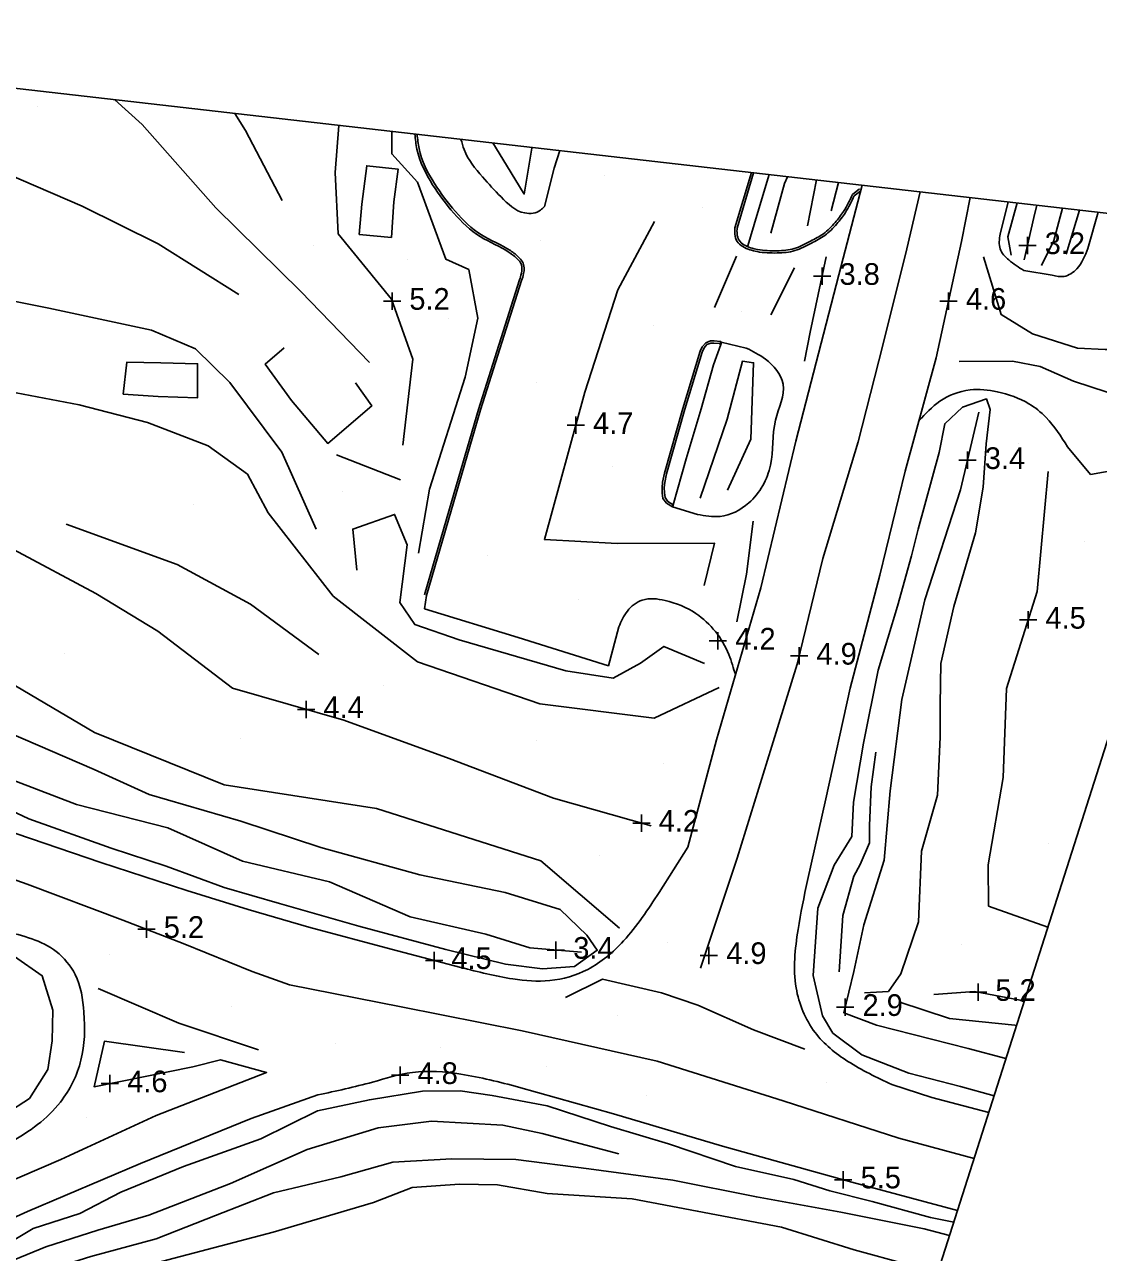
# Model space of a CAD drawing. Extents: x 2316231 to 2323598, y 363169 to 371906.
# Drawn here: x 2321056.2 to 2321303.9, y 371622.5 to 371905.8 of the extents above; entities that cross this region are included whole.
import ezdxf

# ---------------------------------------------------------------- set-up
doc = ezdxf.new("R2010")
doc.units = 0
for name, color, linetype in [('RD_DTM_BkLn1', 7, 'Continuous'), ('RD_DTM_Spot', 7, 'Continuous'), ('RD_DTM_TinHull', 7, 'Continuous'), ('RD_DTM_Void', 7, 'Continuous'), ('RD_EX_H2O', 7, 'Continuous'), ('RD_EX_Road', 7, 'Continuous')]:
    doc.layers.add(name, color=color, linetype=linetype)

msp = doc.modelspace()

# ---------------------------------------------------------------- linework, layer by layer
at = {"layer": 'RD_DTM_BkLn1'}
for p, q in [((2321238.863, 371869.97), (2321236.844, 371859.376)), ((2321242.317, 371862.865), (2321243.955, 371869.387)), ((2321299.568, 371863.027), (2321296.495, 371852.85)), ((2321220.457, 371852.373), (2321215.373, 371840.523)), ((2321228.33, 371838.829), (2321233.828, 371849.672)), ((2321142.92, 371800.768), (2321128.145, 371806.595))]:
    msp.add_line(p, q, dxfattribs=at)
for points in [[(2321200.755, 371720.962), (2321178.245, 371727.364), (2321154.142, 371736.473), (2321129.827, 371745.326), (2321104.183, 371752.718), (2321086.946, 371765.902), (2321072.634, 371774.586), (2321053.696, 371784.724), (2321034.554, 371792.143), (2321011.385, 371803.02), (2321000.166, 371815.454), (2320989.235, 371838.029), (2320977.702, 371852.426), (2320975.22, 371867.477), (2320972.951, 371892.004), (2320973.482, 371900.318)], [(2321112.371, 371793.18), (2321107.677, 371802.058), (2321098.592, 371808.631), (2321084.549, 371813.986), (2321068.841, 371818.114), (2321046.119, 371822.417), (2321024.011, 371829.564), (2321007.375, 371838.157), (2320996.479, 371853.659), (2320986.474, 371871.338), (2320983.378, 371890.851), (2320983.909, 371899.126)], [(2321123.505, 371789.385), (2321115.531, 371807.167), (2321103.554, 371823.224), (2321095.62, 371830.979), (2321085.469, 371835.306), (2321061.783, 371840.373), (2321027.056, 371847.321), (2321012.224, 371866.047), (2321004.626, 371893.2), (2321004.563, 371896.764)], [(2321179.795, 371701.686), (2321167.05, 371705.574), (2321147.408, 371709.681), (2321124.582, 371715.945), (2321106.121, 371722.053), (2321084.963, 371728.189), (2321072.242, 371733.98), (2321052.524, 371742.465), (2321033.56, 371748.576), (2321015.618, 371753.723), (2320995.155, 371760.812), (2320974.152, 371769.177), (2320964.545, 371785.417), (2320960.663, 371805.94), (2320959.939, 371816.706), (2320943.255, 371819.849), (2320920.857, 371823.589), (2320896.492, 371835.56), (2320868.581, 371846.187), (2320850.246, 371852.06), (2320835.078, 371861.975), (2320822.796, 371874.183), (2320812.266, 371892.11), (2320812.342, 371893.23)], [(2321105.623, 371843.544), (2321087.022, 371855.221), (2321069.488, 371863.914), (2321044.636, 371874.603), (2321035.867, 371886.718), (2321034.459, 371893.345)], [(2321135.753, 371827.86), (2321119.95, 371844.246), (2321100.36, 371863.574), (2321083.372, 371882.745), (2321077.025, 371888.477)], [(2321115.627, 371865.261), (2321107.198, 371881.354), (2321104.685, 371885.314)], [(2321143.509, 371808.807), (2321145.762, 371828.601), (2321140.821, 371842.465), (2321128.592, 371857.566), (2321127.901, 371871.66), (2321128.689, 371882.569)], [(2321140.954, 371881.166), (2321140.921, 371875.976), (2321146.82, 371869.46), (2321153.358, 371851.722), (2321158.665, 371849.306), (2321160.776, 371838.098), (2321157.851, 371824.484), (2321149.618, 371798.624), (2321147.06, 371783.874)], [(2321173.309, 371877.466), (2321173.239, 371877.284), (2321171.49, 371866.72), (2321167.354, 371873.389), (2321164.227, 371878.505)], [(2321228.358, 371857.668), (2321231.491, 371869.122), (2321232.222, 371870.729)], [(2321212.11, 371688.1), (2321220.62, 371713.468), (2321228.573, 371739.318), (2321234.427, 371758.248), (2321240.386, 371782.664), (2321248.521, 371809.528), (2321254.21, 371831.891), (2321259.758, 371854.103), (2321262.814, 371867.231)], [(2321285.187, 371864.672), (2321283.063, 371856.882), (2321283.806, 371852.652)], [(2321290.84, 371850.248), (2321293.679, 371855.996), (2321295.676, 371863.473)], [(2321213.008, 371776.409), (2321215.383, 371786.152), (2321192.924, 371786.064), (2321176.133, 371787.013), (2321185.446, 371821.002), (2321193.058, 371844.636), (2321201.494, 371860.386)], [(2321277.418, 371852.203), (2321281.511, 371838.905), (2321288.731, 371834.446), (2321299.098, 371831.134), (2321305.469, 371830.836), (2321310.617, 371830.872), (2321315.251, 371845.27), (2321319.644, 371860.416), (2321319.73, 371860.722)], [(2321241.163, 371852.239), (2321237.467, 371834.894), (2321236.116, 371828.133)], [(2321212.042, 371796.586), (2321218.276, 371814.801), (2321221.794, 371828.132), (2321224.371, 371827.8), (2321223.779, 371810.167), (2321218.403, 371798.4)], [(2321271.834, 371828.088), (2321284.079, 371828.184), (2321290.48, 371826.941), (2321298.15, 371823.541), (2321305.919, 371820.981), (2321313.887, 371820.322), (2321322.478, 371820.302), (2321328.803, 371821.825), (2321332.136, 371822.687)], [(2321277.354, 371799.081), (2321278.073, 371809.068), (2321278.976, 371817.012), (2321278.105, 371819.468), (2321272.607, 371817.566), (2321268.496, 371813.741), (2321267.204, 371807.084), (2321262.374, 371789.397), (2321260.794, 371783.279), (2321257.567, 371771.604), (2321253.153, 371756.913), (2321249.752, 371740.056), (2321247.399, 371726.403), (2321247.08, 371718.503), (2321242.975, 371711.911), (2321239.175, 371701.955), (2321238.106, 371686.426), (2321240.252, 371677.086), (2321242.701, 371673.148), (2321249.345, 371668.156), (2321260.173, 371663.919), (2321272.082, 371660.795), (2321279.857, 371658.702)], [(2321292.342, 371802.696), (2321289.805, 371775.013), (2321282.692, 371752.636), (2321281.929, 371732.109), (2321278.518, 371711.961), (2321278.585, 371702.436), (2321292.249, 371697.57)], [(2321277.354, 371799.081), (2321275.582, 371788.576), (2321270.558, 371771.59), (2321267.59, 371758.395), (2321267.458, 371748.953), (2321267.422, 371741.436), (2321266.845, 371728.04), (2321263.084, 371715.096), (2321262.395, 371698.782), (2321258.372, 371686.774), (2321255.486, 371682.765), (2321249.986, 371682.462)], [(2321213.067, 371758.433), (2321203.684, 371762.346), (2321198.325, 371758.458), (2321191.964, 371755.009), (2321181.038, 371756.703), (2321156.444, 371763.877), (2321146.206, 371767.398), (2321142.772, 371772.463), (2321144.434, 371785.806), (2321141.562, 371792.828), (2321131.921, 371789.424), (2321132.887, 371779.962)], [(2321124.124, 371760.514), (2321108.301, 371772.103), (2321091.435, 371781.281), (2321065.78, 371790.587)], [(2321224.275, 371791.266), (2321222.737, 371779.054), (2321220.518, 371767.991)], [(2321179.795, 371701.686), (2321185.884, 371695.729), (2321188.337, 371692.258), (2321183.106, 371688.486), (2321175.679, 371687.939), (2321167.189, 371689.068), (2321153.378, 371692.449), (2321133.336, 371697.819), (2321114.998, 371703.074), (2321102.287, 371706.763), (2321088.883, 371711.682), (2321076.175, 371715.803), (2321057.228, 371722.579), (2321045.229, 371728.155), (2321025.735, 371735.156), (2321007.369, 371741.601), (2320988.308, 371748.938), (2320969.756, 371757.218), (2320953.885, 371763.355)], [(2321244.135, 371687.298), (2321244.954, 371700.261), (2321247.534, 371709.36), (2321248.94, 371712.036), (2321251.144, 371717.052), (2321251.1, 371721.068), (2321251.531, 371729.936), (2321252.598, 371737.925)], [(2321275.234, 371644.2), (2321257.916, 371648.864), (2321231.207, 371657.534), (2321202.108, 371666.629), (2321170.999, 371673.694), (2321143.068, 371679.232), (2321117.292, 371684.266), (2321108.744, 371687.322), (2321092.83, 371693.786), (2321078.916, 371699.222), (2321056.815, 371707.489), (2321037.611, 371714.29)], [(2321051.92, 371654.492), (2321057.335, 371658.017), (2321061.557, 371664.714), (2321062.569, 371671.384), (2321062.696, 371678.398), (2321060.25, 371686.351), (2321053.905, 371690.793)], [(2321236.233, 371669.443), (2321224.356, 371673.862), (2321211.53, 371679.548), (2321203.156, 371682.45), (2321189.554, 371685.561), (2321180.994, 371681.368)], [(2321110.168, 371669.266), (2321091.824, 371675.443), (2321073.176, 371683.455)], [(2321265.963, 371682.055), (2321275.376, 371682.73), (2321285.845, 371680.736), (2321286.768, 371680.377)], [(2321257.875, 371680.369), (2321269.558, 371676.499), (2321284.617, 371674.989), (2321285.018, 371674.889)], [(2320771.018, 371541.569), (2320783.675, 371550.404), (2320801.239, 371560.761), (2320826.41, 371568.664), (2320849.036, 371574.832), (2320874.491, 371581.496), (2320897.809, 371588.162), (2320921.351, 371595.165), (2320947.344, 371602.117), (2320966.599, 371608.471), (2320994.344, 371617.396), (2321011.536, 371622.642), (2321028.89, 371629.323), (2321045.554, 371635.787), (2321064.61, 371643.963), (2321086.608, 371654.116), (2321112.049, 371664.025), (2321101.375, 371666.954), (2321095.027, 371665.337), (2321072.235, 371660.757), (2321074.638, 371671.271), (2321093.099, 371668.677)], [(2321051.665, 371624.122), (2321058.169, 371628.06), (2321068.988, 371631.515), (2321078.381, 371636.427), (2321092.859, 371642.391), (2321110.677, 371648.743), (2321123.804, 371655.206), (2321135.75, 371657.755), (2321148.007, 371659.73), (2321156.704, 371659.837), (2321164.086, 371658.727), (2321176.77, 371656.381), (2321191.4, 371651.582), (2321204.751, 371647.609), (2321220.23, 371642.384), (2321233.646, 371639.356), (2321241.975, 371636.769), (2321251.764, 371634.29), (2321265.198, 371630.561), (2321270.563, 371629.546)], [(2321193.285, 371645.255), (2321175.608, 371649.98), (2321166.563, 371651.871), (2321150.122, 371652.83), (2321137.763, 371651.299), (2321121.365, 371646.281), (2321103.712, 371638.434), (2321084.895, 371631.121), (2321073.13, 371627.695), (2321061.106, 371623.839), (2321053.78, 371620.828)], [(2321063.73, 371593.139), (2321061.14, 371600.19), (2321058.627, 371610.56), (2321060.823, 371612.507), (2321069.644, 371615.625), (2321089.252, 371620.809), (2321113.526, 371627.223), (2321136.694, 371634.077), (2321145.623, 371637.533), (2321156.507, 371638.314), (2321165.295, 371638.129), (2321176.756, 371636.164), (2321196.393, 371634.87), (2321211.398, 371632.088), (2321230.796, 371628.344), (2321247.571, 371623.146), (2321259.934, 371619.774), (2321266.861, 371617.936)]]:
    msp.add_lwpolyline(points, dxfattribs=at)
at = {"layer": 'RD_DTM_Spot'}
for p, q in [((2321059.119, 371886.824), (2321059.119, 371886.824)), ((2321190.006, 371870.908), (2321190.006, 371870.908)), ((2321212.651, 371863.688), (2321212.651, 371863.688)), ((2321122.891, 371854.965), (2321122.891, 371854.965)), ((2321175.213, 371855.922), (2321175.213, 371855.922)), ((2321144.638, 371851.615), (2321144.638, 371851.615)), ((2321153.994, 371838.119), (2321153.994, 371838.119)), ((2321221.519, 371839.713), (2321221.519, 371839.713)), ((2321201.281, 371836.506), (2321201.281, 371836.506)), ((2321174.22, 371823.222), (2321174.22, 371823.222)), ((2321285.579, 371809.23), (2321285.579, 371809.23)), ((2321191.825, 371803.813), (2321191.825, 371803.813)), ((2321129.491, 371798.089), (2321129.491, 371798.089)), ((2321095.212, 371795.03), (2321095.212, 371795.03)), ((2321300.771, 371786.615), (2321300.771, 371786.615)), ((2321162.943, 371783.445), (2321162.943, 371783.445)), ((2321183.945, 371773.072), (2321183.945, 371773.072)), ((2321065.446, 371760.649), (2321065.446, 371760.649)), ((2321138.984, 371753.391), (2321138.984, 371753.391)), ((2321105.964, 371741.069), (2321105.964, 371741.069)), ((2321174.316, 371740.743), (2321174.316, 371740.743)), ((2321203.603, 371735.324), (2321203.603, 371735.324)), ((2321292.44, 371716.785), (2321292.44, 371716.785)), ((2321188.839, 371714.012), (2321188.839, 371714.012)), ((2321204.445, 371694.056), (2321204.445, 371694.056)), ((2321272.342, 371693.64), (2321272.342, 371693.64)), ((2321075.76, 371691.329), (2321075.76, 371691.329)), ((2321223.876, 371688.094), (2321223.876, 371688.094)), ((2321104, 371679.31), (2321104, 371679.31)), ((2321193.071, 371677.146), (2321193.071, 371677.146)), ((2321127.967, 371670.715), (2321127.967, 371670.715)), ((2321152.252, 371669.881), (2321152.252, 371669.881)), ((2321176.514, 371665.545), (2321176.514, 371665.545)), ((2321241.215, 371661.765), (2321241.215, 371661.765)), ((2321199.699, 371658.777), (2321199.699, 371658.777)), ((2321070.427, 371653.696), (2321070.427, 371653.696))]:
    msp.add_line(p, q, dxfattribs=at)
at = {"layer": 'RD_DTM_TinHull'}
msp.add_lwpolyline([(2319782.271, 371232.132), (2319735.05, 371773.026), (2320925.274, 371905.831), (2321343.399, 371858.015), (2321109.741, 371125.092), (2321259.088, 370783.878), (2321451.866, 370308.131), (2321545.882, 369878.312), (2321496.483, 369600.925), (2321592.742, 369376.322), (2321772.553, 369180.585), (2321930.831, 369046.826), (2322410.389, 369187.058), (2322700.489, 369322.074), (2323031.423, 369488.086), (2323384.71, 369626.658), (2323598.112, 369182.404), (2323506.079, 369141.824), (2322749.057, 368805.183), (2322437.788, 368637.943)], dxfattribs=at)
at = {"layer": 'RD_DTM_Void'}
for p, q in [((2321287.544, 371852.869), (2321287.544, 371856.869)), ((2321285.544, 371854.869), (2321289.544, 371854.869)), ((2321240.212, 371845.775), (2321240.212, 371849.775)), ((2321238.212, 371847.775), (2321242.212, 371847.775)), ((2321140.976, 371840.029), (2321140.976, 371844.029)), ((2321269.367, 371840.031), (2321269.367, 371844.031)), ((2321138.976, 371842.029), (2321142.976, 371842.029)), ((2321267.367, 371842.031), (2321271.367, 371842.031)), ((2321183.363, 371811.4), (2321183.363, 371815.4)), ((2321181.363, 371813.4), (2321185.363, 371813.4)), ((2321273.731, 371803.29), (2321273.731, 371807.29)), ((2321271.731, 371805.29), (2321275.731, 371805.29)), ((2321287.719, 371766.451), (2321287.719, 371770.451)), ((2321285.719, 371768.451), (2321289.719, 371768.451)), ((2321214.173, 371763.62), (2321218.173, 371763.62)), ((2321216.173, 371761.62), (2321216.173, 371765.62)), ((2321234.893, 371758.158), (2321234.893, 371762.158)), ((2321232.893, 371760.158), (2321236.893, 371760.158)), ((2321121.156, 371745.826), (2321121.156, 371749.826)), ((2321119.156, 371747.826), (2321123.156, 371747.826)), ((2321198.503, 371719.602), (2321198.503, 371723.602)), ((2321196.503, 371721.602), (2321200.503, 371721.602)), ((2321084.316, 371695.112), (2321084.316, 371699.112)), ((2321082.316, 371697.112), (2321086.316, 371697.112)), ((2321178.795, 371690.302), (2321178.795, 371694.302)), ((2321214.079, 371689.076), (2321214.079, 371693.076)), ((2321148.675, 371689.919), (2321152.675, 371689.919)), ((2321150.675, 371687.919), (2321150.675, 371691.919)), ((2321176.795, 371692.302), (2321180.795, 371692.302)), ((2321212.079, 371691.076), (2321216.079, 371691.076)), ((2321276.17, 371680.579), (2321276.17, 371684.579)), ((2321245.521, 371677.102), (2321245.521, 371681.102)), ((2321274.17, 371682.579), (2321278.17, 371682.579)), ((2321243.521, 371679.102), (2321247.521, 371679.102)), ((2321142.869, 371661.395), (2321142.869, 371665.395)), ((2321073.889, 371661.492), (2321077.889, 371661.492)), ((2321075.889, 371659.492), (2321075.889, 371663.492)), ((2321140.869, 371663.395), (2321144.869, 371663.395)), ((2321243.083, 371639.32), (2321247.083, 371639.32)), ((2321245.083, 371637.32), (2321245.083, 371641.32))]:
    msp.add_line(p, q, dxfattribs=at)
at = {"layer": 'RD_EX_H2O'}
for points in [[(2321289.755, 371864.15), (2321289.01, 371861.338), (2321286.787, 371851.524)], [(2321276.334, 371816.433), (2321272.145, 371798.496), (2321263.88, 371773.139), (2321258.595, 371750.084), (2321255.867, 371729.056), (2321254.515, 371713.05), (2321249.842, 371698.081), (2321247.52, 371687.334), (2321245.205, 371677.801)], [(2320975.167, 371760.066), (2320997.012, 371753.726), (2321017.396, 371745.318), (2321040.404, 371736.52), (2321068.221, 371725.905), (2321089.256, 371720.528), (2321106.47, 371712.806), (2321126.574, 371708.065), (2321145.151, 371699.961), (2321162.646, 371695.926), (2321172.757, 371692.779), (2321184.669, 371691.838)], [(2321282.592, 371667.278), (2321273.925, 371669.573), (2321252.716, 371674.986), (2321245.205, 371677.801)], [(2321269.57, 371626.433), (2321263.711, 371628.014), (2321244.476, 371631.85), (2321225.041, 371635.361), (2321205.747, 371639.198), (2321186.376, 371641.845), (2321169.511, 371643.961), (2321154.781, 371644.115), (2321141.201, 371643.328), (2321129.157, 371639.985), (2321113.643, 371636.316), (2321100.221, 371631.08), (2321086.588, 371625.682), (2321071.492, 371621.589), (2321060.708, 371618.204), (2321058.853, 371616.628), (2321051.953, 371613.31)]]:
    msp.add_lwpolyline(points, dxfattribs=at)
at = {"layer": 'RD_EX_Road'}
for p, q in [((2321223.893, 371871.681), (2321220.079, 371858.924)), ((2321224.398, 371871.624), (2321220.579, 371858.851)), ((2321247.224, 371866.649), (2321248.813, 371867.894)), ((2321247.616, 371866.321), (2321249.121, 371867.5)), ((2321283.115, 371864.909), (2321281.258, 371857.501)), ((2321301.499, 371854.136), (2321303.892, 371862.533)), ((2321286.701, 371849.096), (2321293.254, 371847.992)), ((2321222.689, 371831.196), (2321216.916, 371832.569)), ((2321205.702, 371794.537), (2321211.41, 371792.808))]:
    msp.add_line(p, q, dxfattribs=at)
for points in [[(2321156.888, 371688.306), (2321140.796, 371692.484), (2321121.825, 371697.544), (2321107.775, 371701.627), (2321093.621, 371706.037), (2321073.808, 371712.492), (2321051.014, 371720.238), (2321027.354, 371729.239), (2321005.817, 371736.382), (2320981.614, 371746.192), (2320961.108, 371755.628), (2320941.263, 371764.499), (2320922.543, 371773.876), (2320894.25, 371786.736), (2320869.132, 371799.622), (2320840.63, 371814.502), (2320813.598, 371827.412), (2320781.42, 371844.125), (2320746.784, 371861.671), (2320732.166, 371870.03), (2320710.002, 371881.262), (2320708.823, 371881.679)], [(2321179.689, 371876.737), (2321178.392, 371872.675), (2321176.164, 371863.877)], [(2321133.376, 371857.36), (2321140.831, 371856.728), (2321141.433, 371864.942), (2321142.38, 371872.476), (2321135.149, 371873.27), (2321134.052, 371864.418), (2321133.376, 371857.36)], [(2321223.027, 371854.744), (2321225.163, 371861.739), (2321227.947, 371871.218)], [(2321249.449, 371868.759), (2321244.066, 371848.053), (2321234.165, 371809.738), (2321226.066, 371775.834), (2321215.836, 371740.789), (2321209.233, 371716.016), (2321202.582, 371705.577)], [(2321236.824, 371708.379), (2321241.089, 371727.168), (2321246.636, 371752.753), (2321253.528, 371778.785), (2321259.356, 371802.793), (2321266.493, 371828.905), (2321272.375, 371855.772), (2321274.342, 371865.912)], [(2321148.454, 371774.256), (2321154.769, 371795.926), (2321160.919, 371817.054), (2321170.403, 371846.918)], [(2321148.934, 371774.116), (2321155.249, 371795.786), (2321161.397, 371816.909), (2321170.882, 371846.776)], [(2321205.702, 371794.537), (2321204.295, 371795.41), (2321203.473, 371796.489), (2321203.318, 371797.786), (2321203.268, 371799), (2321203.393, 371800.272), (2321203.803, 371802.324), (2321208.032, 371817.272), (2321212.062, 371830.448), (2321212.524, 371831.484), (2321213.336, 371832.401), (2321214.471, 371832.86), (2321215.276, 371832.832), (2321216.758, 371832.705)], [(2321205.871, 371795.021), (2321204.637, 371795.786), (2321203.954, 371796.684), (2321203.817, 371797.826), (2321203.769, 371798.986), (2321203.888, 371800.198), (2321204.289, 371802.206), (2321208.511, 371817.131), (2321212.532, 371830.272), (2321212.95, 371831.21), (2321213.632, 371831.981), (2321214.56, 371832.357), (2321215.246, 371832.332), (2321216.554, 371832.221), (2321216.802, 371832.006)], [(2321205.871, 371795.021), (2321208.82, 371805.606), (2321212.28, 371817.175), (2321215.147, 371827.288), (2321216.802, 371832.006)], [(2321216.802, 371832.006), (2321216.895, 371832.272), (2321216.758, 371832.705)], [(2321216.758, 371832.705), (2321216.758, 371832.705), (2321217.152, 371832.364)], [(2321132.571, 371823.165), (2321136.319, 371817.853), (2321126.155, 371809.199), (2321117.791, 371819.105), (2321111.729, 371827.49), (2321116.13, 371831.232)], [(2321078.931, 371820.559), (2321087.005, 371820.016), (2321096.096, 371819.701), (2321096.135, 371827.556), (2321087.627, 371827.798), (2321079.807, 371827.954), (2321078.931, 371820.559)], [(2321296.791, 371808.387), (2321302.119, 371802.026), (2321326.958, 371806.444)], [(2321205.702, 371794.537), (2321205.856, 371794.968), (2321205.871, 371795.021)], [(2321216.475, 371752.901), (2321201.488, 371745.773), (2321175.106, 371749.072), (2321146.874, 371758.815), (2321127.397, 371773.952), (2321112.371, 371793.18)], [(2321193.29, 371766.86), (2321190.909, 371757.899), (2321170.069, 371764.384), (2321148.483, 371771.06), (2321148.934, 371774.116)], [(2321193.459, 371697.325), (2321175.292, 371712.909), (2321137.375, 371724.944), (2321102.229, 371730.401), (2321072.379, 371742.523), (2321047.669, 371756.994)], [(2321278.623, 371654.83), (2321265.506, 371658.293), (2321256.246, 371661.283)], [(2320819.073, 371557.502), (2320831.287, 371561.127), (2320851.121, 371566.881), (2320878.222, 371573.733), (2320905.248, 371581.507), (2320936.447, 371590.235), (2320964.985, 371598.945), (2320981.253, 371603.812), (2321005.933, 371611.695), (2321031.166, 371620.274), (2321056.863, 371631.979), (2321082.918, 371643.039), (2321108.478, 371653.438), (2321123.898, 371658.882)], [(2321170.191, 371660.684), (2321192.096, 371654.542), (2321217.226, 371647.049), (2321247.077, 371638.767), (2321271.421, 371632.239)]]:
    msp.add_lwpolyline(points, dxfattribs=at)
for points in [[(2321170.403, 371846.918), (2321170.822, 371848.433), (2321170.763, 371850.595), (2321169.979, 371851.66), (2321168.009, 371853.251), (2321161.31, 371856.918), (2321155.242, 371862.328), (2321150.352, 371868.877), (2321146.735, 371877.069), (2321146.244, 371880.561)], [(2321170.882, 371846.776), (2321171.324, 371848.372), (2321171.258, 371850.765), (2321170.344, 371852.009), (2321168.289, 371853.668), (2321161.601, 371857.329), (2321155.612, 371862.668), (2321150.786, 371869.13), (2321147.22, 371877.208), (2321146.757, 371880.503)], [(2321176.164, 371863.877), (2321175.248, 371863.007), (2321171.601, 371862.354), (2321166.128, 371866.055), (2321161.862, 371870.67), (2321157.596, 371876.977), (2321156.888, 371879.344)], [(2321220.079, 371858.924), (2321220.081, 371857.488), (2321220.584, 371855.792), (2321221.907, 371854.605), (2321225.214, 371853.451), (2321229.823, 371853.129), (2321233.924, 371853.675), (2321237.74, 371855.401), (2321240.798, 371857.179), (2321243.582, 371859.846), (2321245.56, 371862.459), (2321247.616, 371866.321)], [(2321220.579, 371858.851), (2321220.581, 371857.561), (2321221.023, 371856.07), (2321222.166, 371855.044), (2321225.316, 371853.945), (2321229.807, 371853.632), (2321233.785, 371854.161), (2321237.511, 371855.846), (2321240.495, 371857.581), (2321243.207, 371860.179), (2321245.137, 371862.729), (2321247.224, 371866.649)], [(2321281.258, 371857.501), (2321281.27, 371854.081), (2321283.25, 371851.523), (2321286.701, 371849.096)], [(2321293.254, 371847.992), (2321296.018, 371847.717), (2321298.96, 371849.495), (2321301.499, 371854.136)], [(2321211.41, 371792.808), (2321216.66, 371792.342), (2321223.263, 371795.451), (2321228.281, 371804.173), (2321229.445, 371814.577), (2321231.203, 371822.888), (2321227.097, 371828.646), (2321222.689, 371831.196)], [(2321262.526, 371814.389), (2321267.316, 371818.908), (2321274.313, 371821.536), (2321280.613, 371821.11), (2321287.903, 371818.343), (2321291.828, 371815.213), (2321296.791, 371808.387)], [(2321220.193, 371755.715), (2321218.683, 371760.498), (2321211.099, 371769.932), (2321203.963, 371772.954), (2321198.711, 371773.047), (2321195.263, 371770.501), (2321193.29, 371766.86)], [(2321256.246, 371661.283), (2321246.102, 371666.624), (2321238.569, 371673.28), (2321234.201, 371683.592), (2321234.649, 371697.012), (2321236.824, 371708.379)], [(2321202.582, 371705.577), (2321194.385, 371694.401), (2321186.125, 371687.825), (2321177.401, 371685.266), (2321168.847, 371685.637), (2321156.888, 371688.306)], [(2321024.577, 371635.655), (2321035.381, 371640.219), (2321052.963, 371647.972), (2321064.497, 371657.236), (2321069.217, 371666.905), (2321069.907, 371677.943), (2321067.874, 371686.664), (2321063.531, 371691.933), (2321051.492, 371696.657)], [(2321123.898, 371658.882), (2321136.465, 371661.836), (2321145.666, 371664.076), (2321156.834, 371663.665), (2321170.191, 371660.684)]]:
    msp.add_spline(points, degree=3, dxfattribs=at)

# ---------------------------------------------------------------- texts
at = {"layer": 'RD_DTM_Void'}
for s, p in [('3.2', (2321291.544, 371852.869)), ('3.8', (2321244.212, 371845.775)), ('5.2', (2321144.976, 371840.029)), ('4.6', (2321273.367, 371840.031)), ('4.7', (2321187.363, 371811.4)), ('3.4', (2321277.731, 371803.29)), ('4.5', (2321291.719, 371766.451)), ('4.2', (2321220.173, 371761.62)), ('4.9', (2321238.893, 371758.158)), ('4.4', (2321125.156, 371745.826)), ('4.2', (2321202.503, 371719.602)), ('5.2', (2321088.316, 371695.112)), ('3.4', (2321182.795, 371690.302)), ('4.5', (2321154.675, 371687.919)), ('4.9', (2321218.079, 371689.076)), ('5.2', (2321280.17, 371680.579)), ('2.9', (2321249.521, 371677.102)), ('4.6', (2321079.889, 371659.492)), ('4.8', (2321146.869, 371661.395)), ('5.5', (2321249.083, 371637.32))]:
    msp.add_text(s, height=5, dxfattribs=at).set_placement(p)

doc.saveas('drawing.dxf')
